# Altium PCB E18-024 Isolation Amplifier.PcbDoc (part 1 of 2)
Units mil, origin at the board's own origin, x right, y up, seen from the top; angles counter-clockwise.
Board outline 5740 x 5970 mil, 4 copper layers (Component Side, V+, V-, Ground), stack 33.234 mil thick; 342 components, 165 nets, 939 pads, 4 vias.
Unrouted connection lines stored in the file: 473.
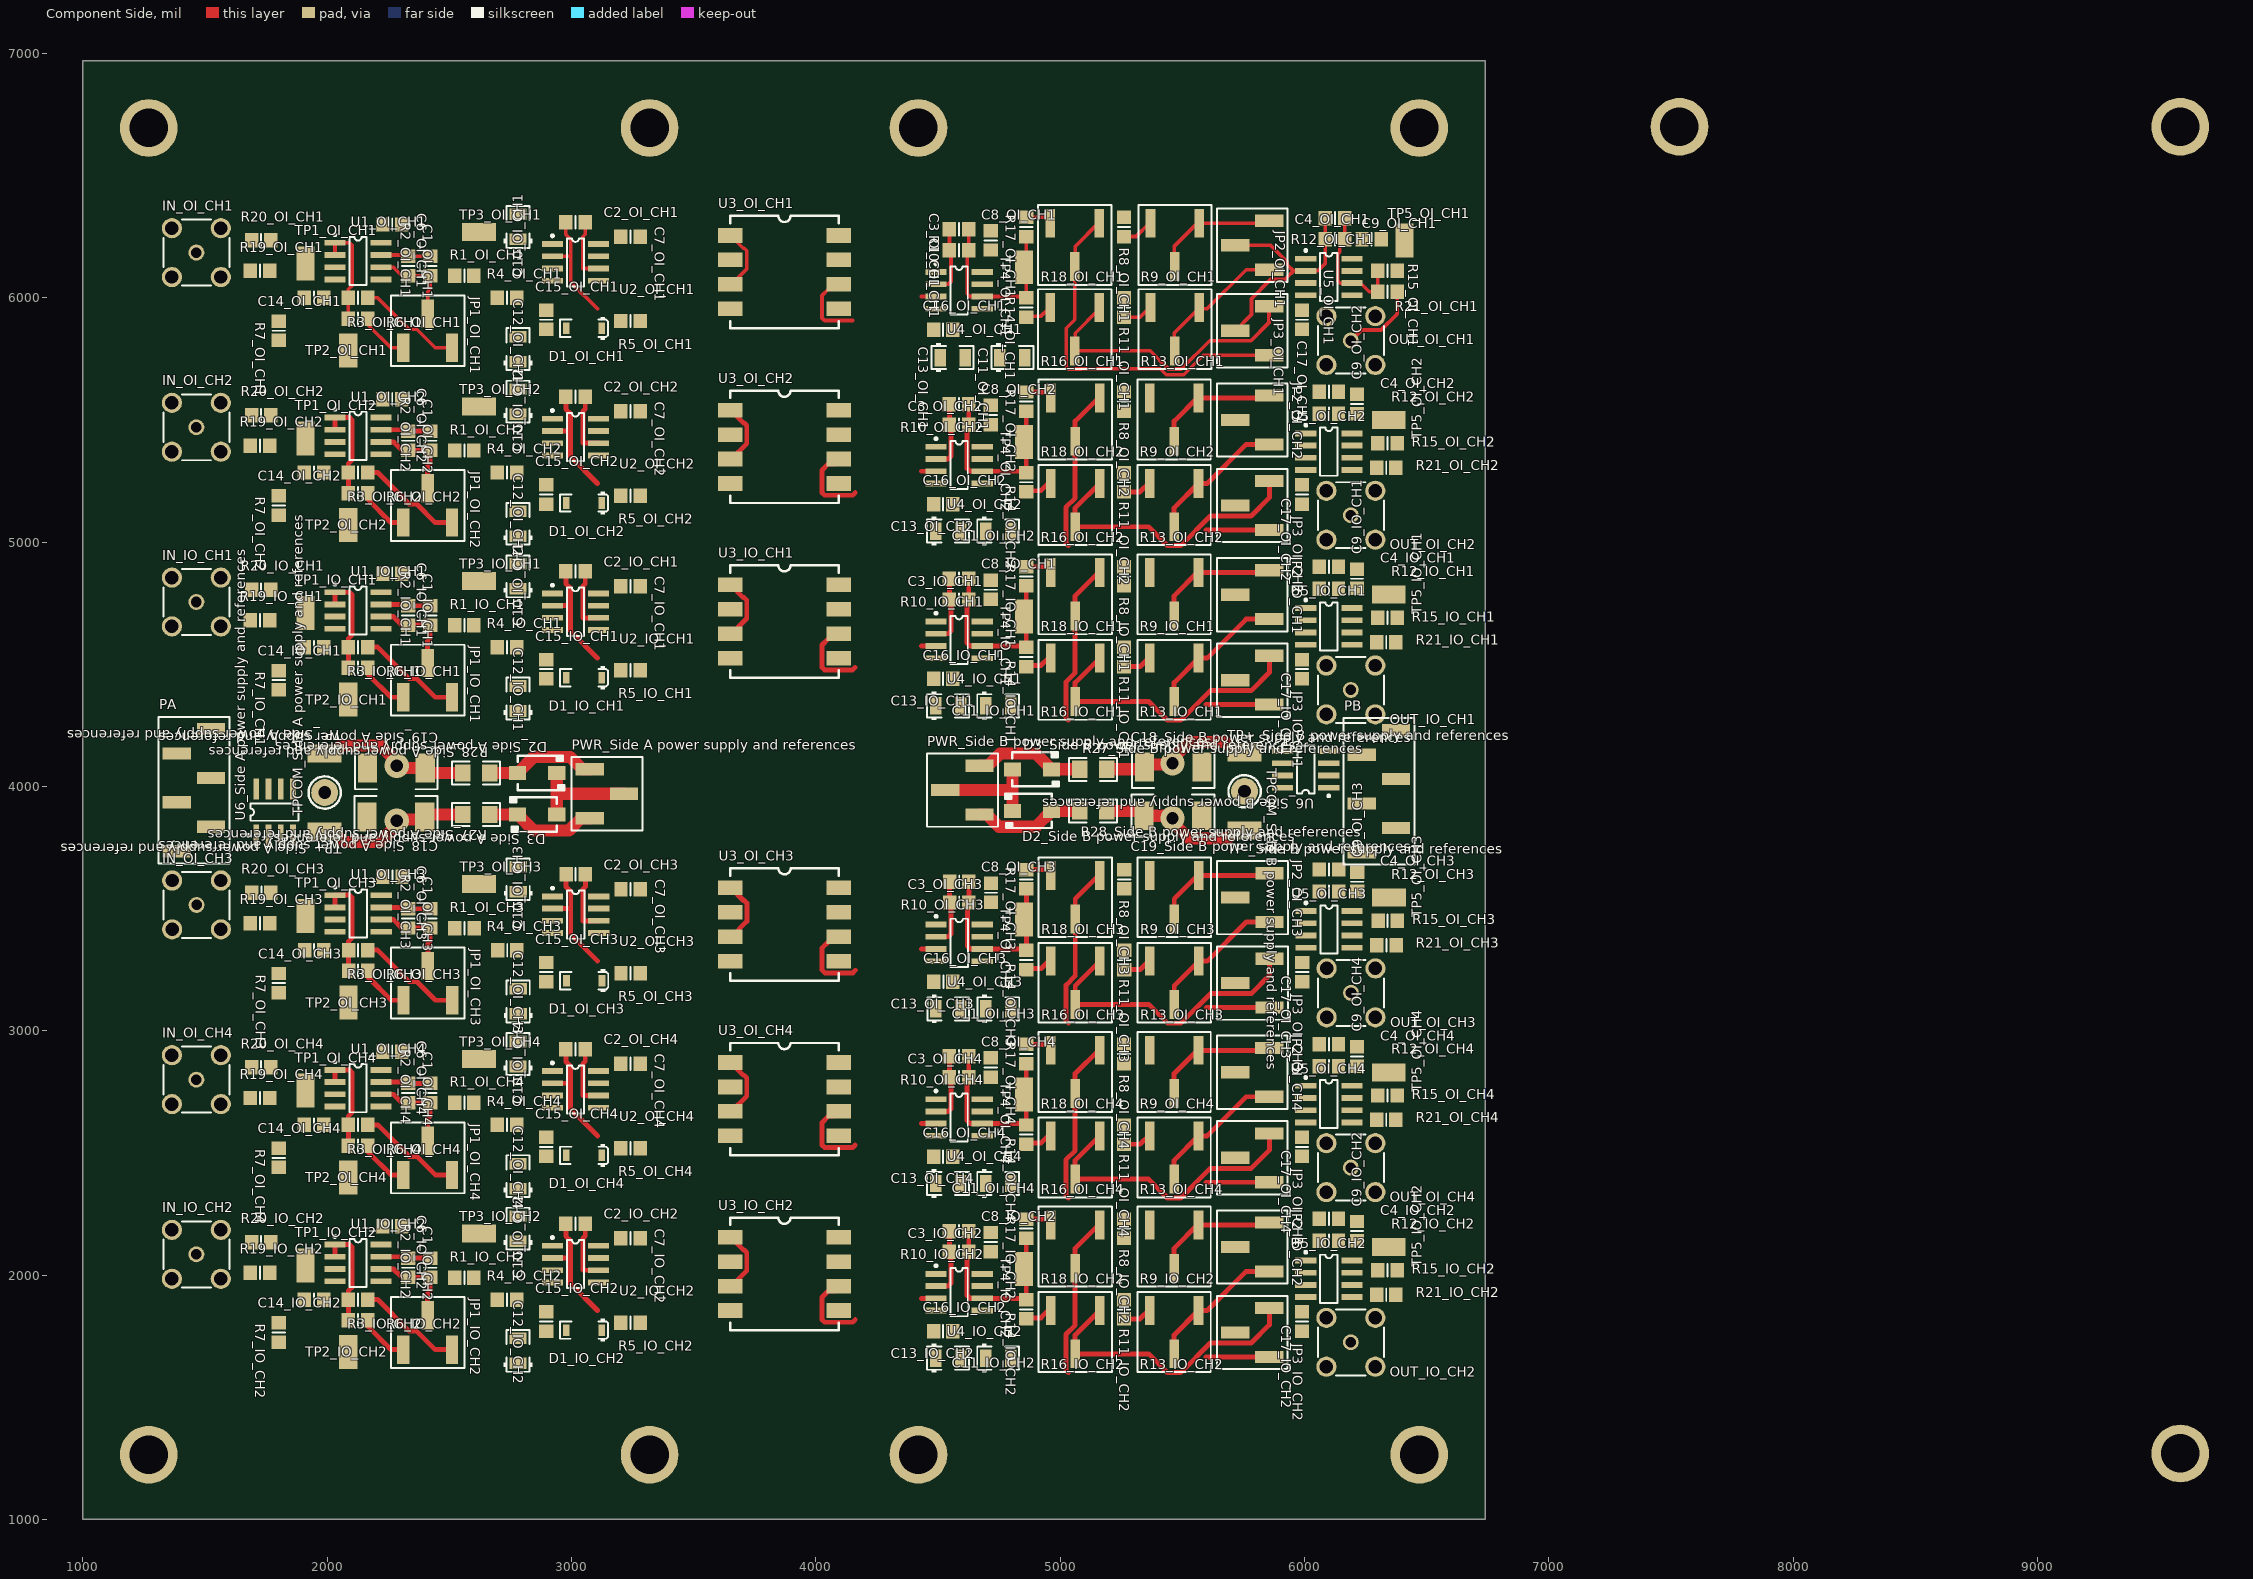
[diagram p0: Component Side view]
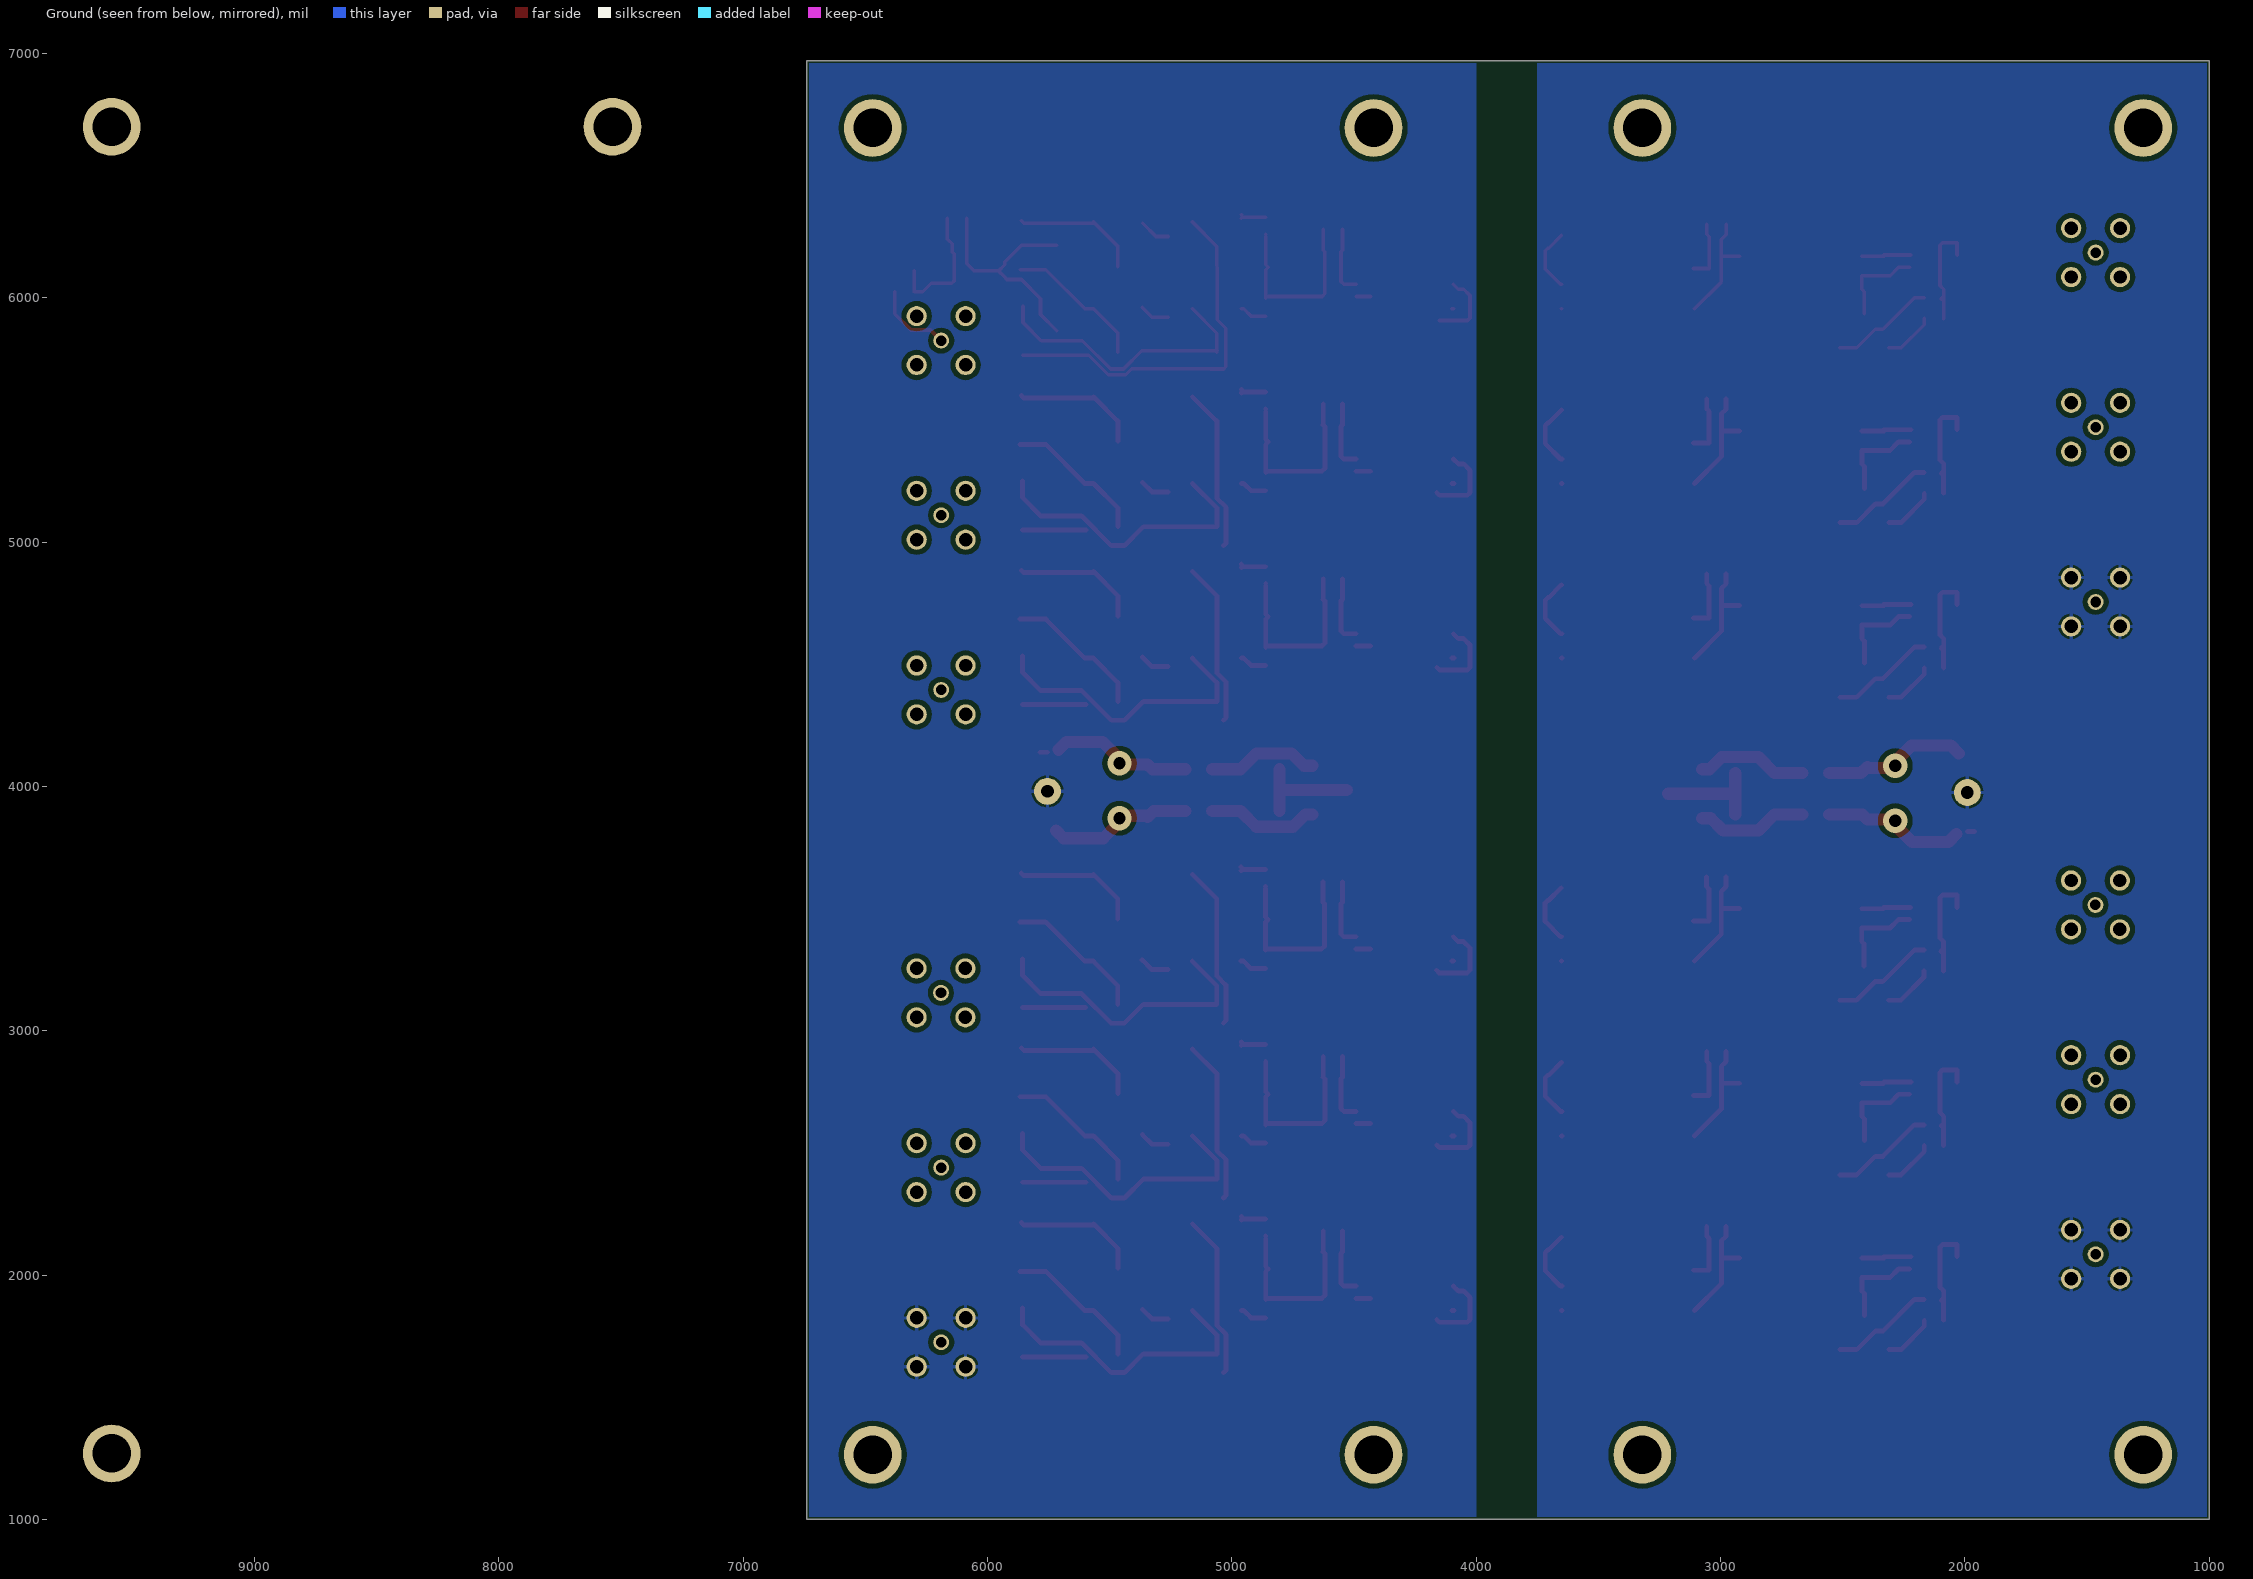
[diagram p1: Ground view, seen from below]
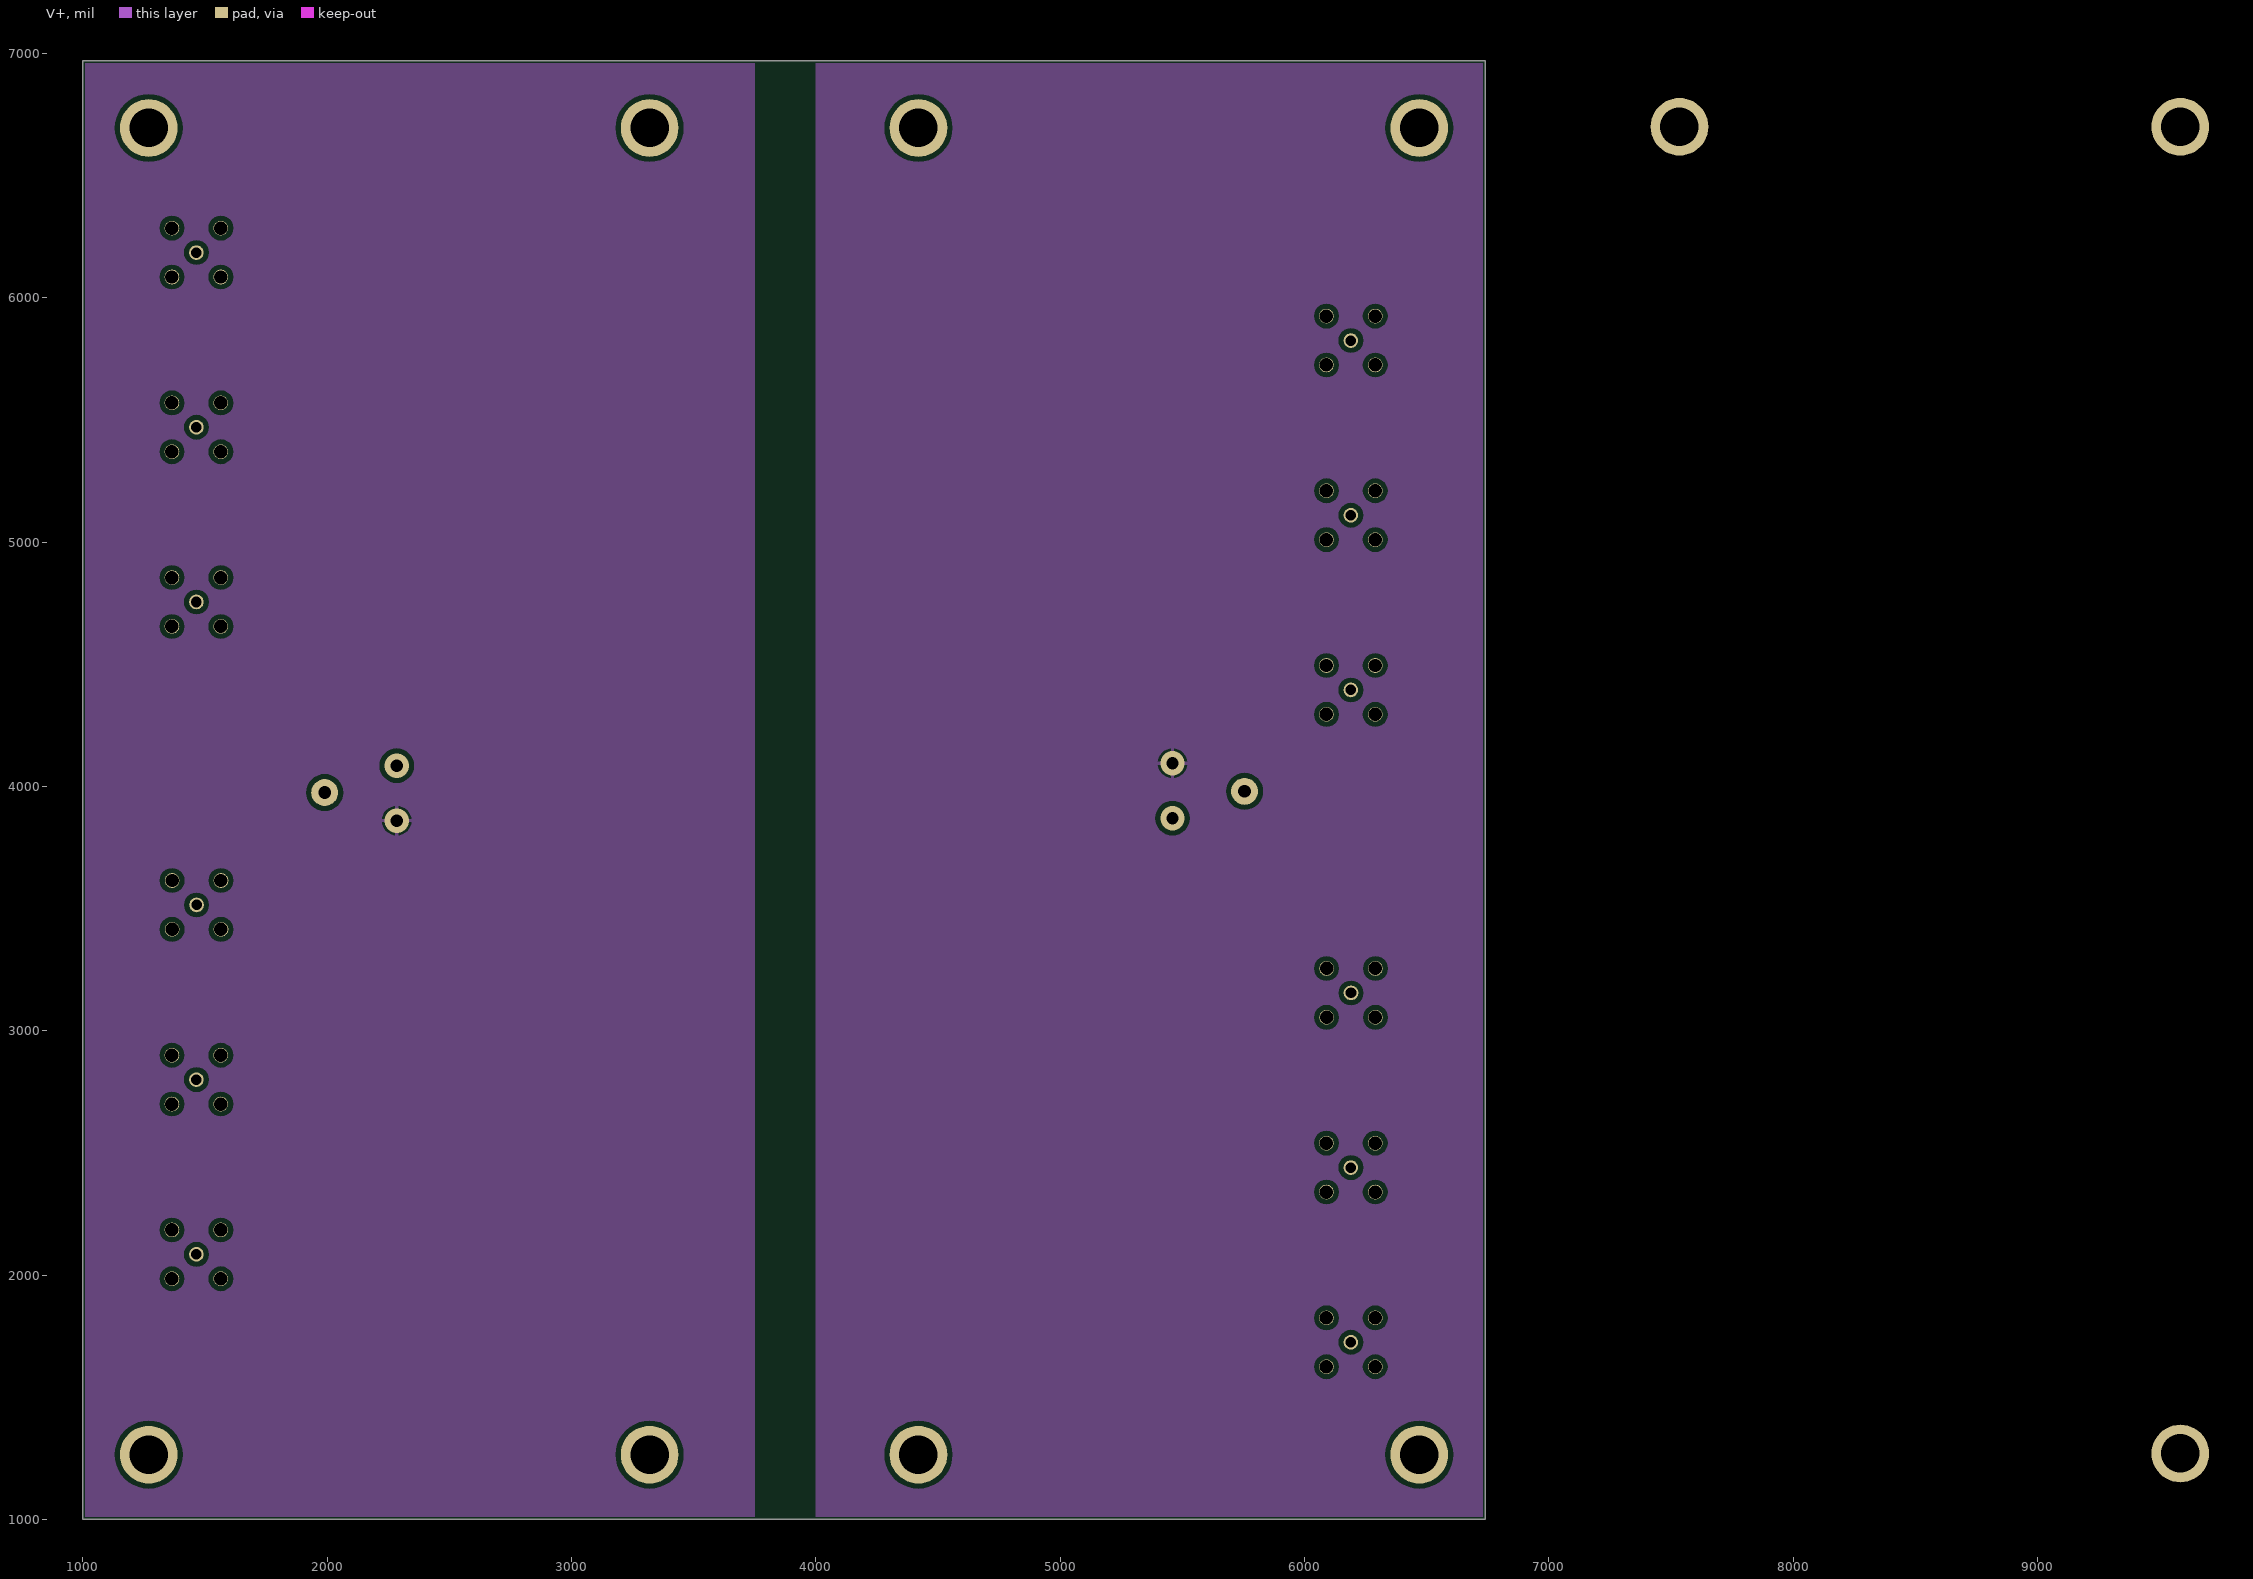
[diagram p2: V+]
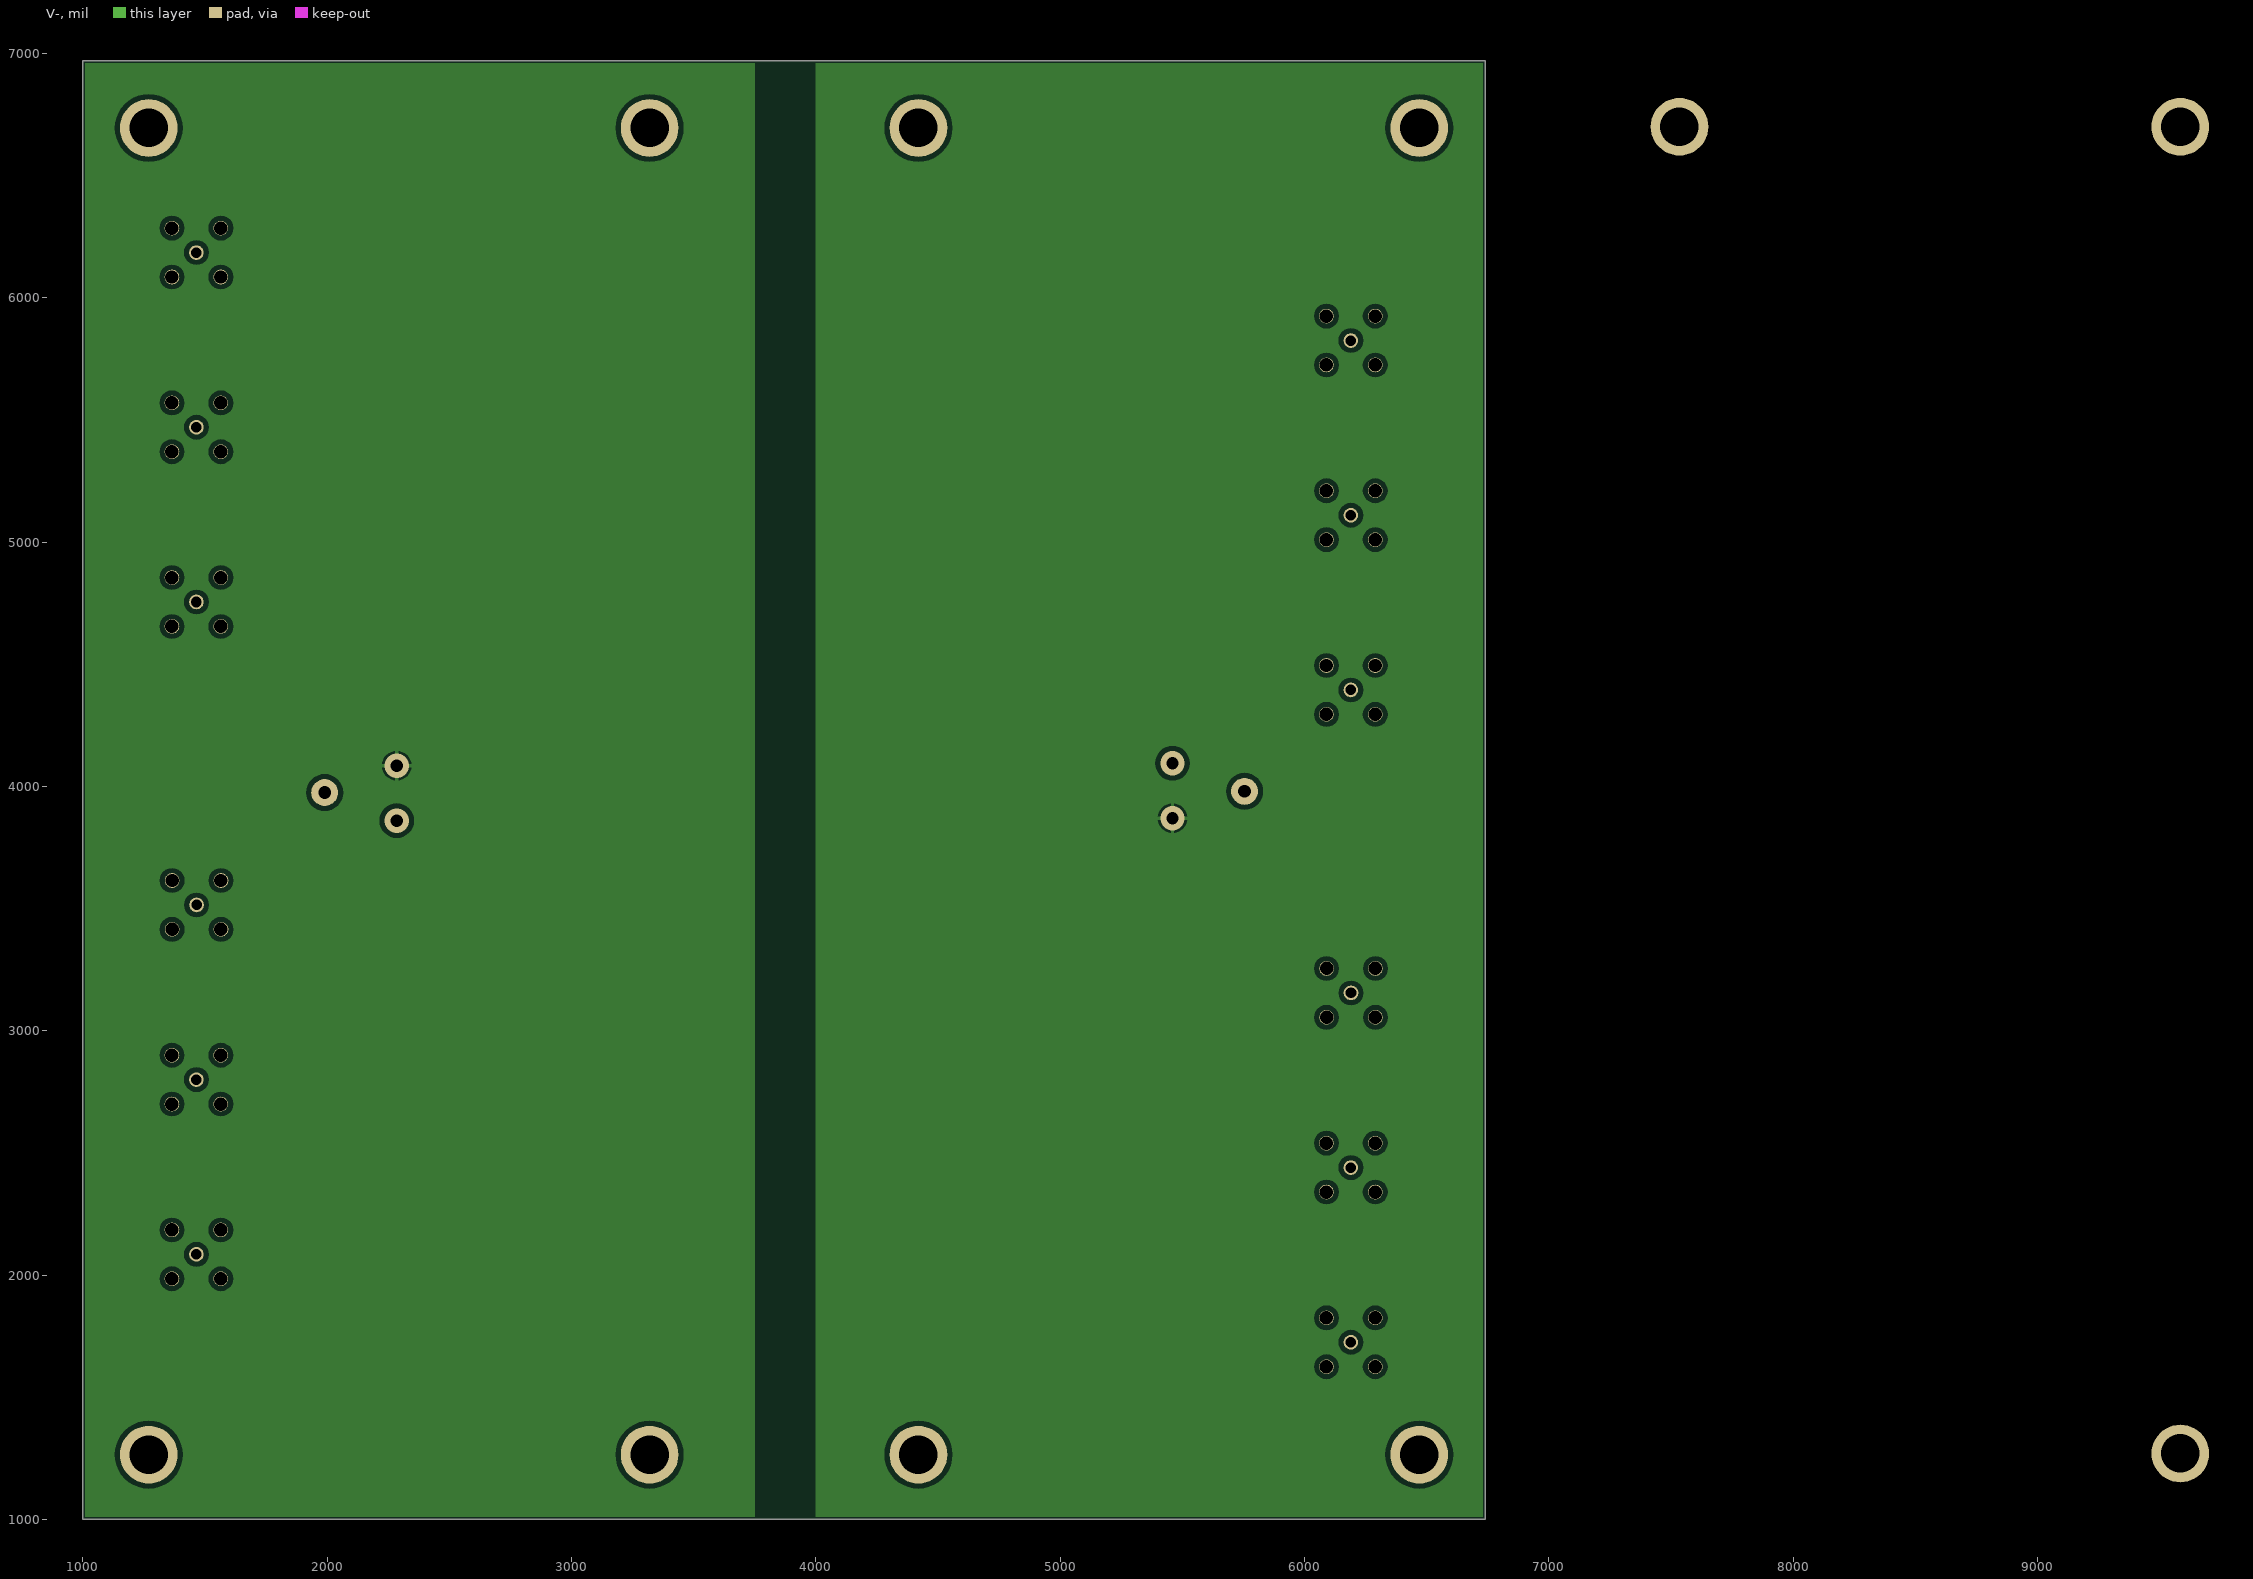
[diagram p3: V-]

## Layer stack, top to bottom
Top Solder: solder mask 0.4, Solder Resist, Dk 3.5
Component Side: signal copper 1.4
Dielectric 1: core 12.6, FR-4, Dk 4.8
V+: signal copper 1.417
Dielectric 4: prepreg 5, Dk 4.2
V-: signal copper 1.417
Dielectric 3: core 10, Dk 4.2
Ground: signal copper 1.4
Bottom Solder: solder mask 0.4, Solder Resist, Dk 3.5

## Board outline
1000,1000 1000,6970 6740,6970 6740,1000

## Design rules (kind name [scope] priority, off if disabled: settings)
AcuteAngle [All] p1: minimum=3.00000000000000E+0001 checktracksonly=FALSE
Clearance Polygon_Pour [InPolygon] p1: gap=20 ignorepadtopadclearanceinfootprint=FALSE except(0: Arc-Hole Track-Hole SMDPad-Hole THPad-Hole Via-Hole Fill-Hole Poly-Hole Region-Hole Text-Hole)
Clearance [All] p2: gap=8 ignorepadtopadclearanceinfootprint=FALSE except(0: Arc-Hole Track-Hole SMDPad-Hole THPad-Hole Via-Hole Fill-Hole Poly-Hole Region-Hole Text-Hole)
HoleSize [All] p1: absolutevalues=TRUE maxlimit=250 minlimit=20 maxpercent=80.000 minpercent=20.000
MinimumAnnularRing [All] p1: minimumring=10
MinimumSolderMaskSliver [All] p1: minsoldermaskwidth=2
MinimumSolderMaskSliver SilkscreenOverComponentPads [All] p2: minsoldermaskwidth=10
PolygonConnect PolygonConnect_1 [All vs IsNamedPolygon('GND_L01_P023') or IsNamedPolygon('GND_L02_P022') or IsNamedPolygon('GND_L03_P021') or IsNamedPolygon('GND_L04_P019')] p1: connectstyle=Direct reliefconductorwidth=10 reliefentries=4 polygonreliefangle="90 Angle" airgapwidth=10
PolygonConnect PolygonViaConnect [(InNet('GND') AND IsVia) OR (InNet('V+') AND IsVia) OR (InNet('V-') AND IsVia)] p2: connectstyle=Direct reliefconductorwidth=15 reliefentries=4 polygonreliefangle="45 Angle" airgapwidth=10
PolygonConnect [All] p3: connectstyle=Relief reliefconductorwidth=15 reliefentries=4 polygonreliefangle="90 Angle" airgapwidth=10
RoomDefinition "E18-024 Isolation Amplifier Top" [InComponentClass('E18-024 Isolation Amplifier Top')] p1: confinementstyle=ConfineOut formatcopy=TRUE lockcomponents=FALSE outline 0,0 160,0 160,265 0,265
RoomDefinition "E18-024 Isolation Amplifier Top A" [InComponentClass('Top A')] p2: confinementstyle=ConfineIn formatcopy=TRUE lockcomponents=FALSE outline 1615,4305 1615,3670 1295,3670 1295,4305
RoomDefinition "Side B power supply and references" [InComponentClass('Side B power supply and references')] p3: confinementstyle=ConfineIn formatcopy=TRUE lockcomponents=FALSE outline 6190,4240 4425,4240 4425,3715 6190,3715
RoomDefinition "Side A power supply and references" [InComponentClass('Side A power supply and references')] p4: confinementstyle=ConfineIn formatcopy=TRUE lockcomponents=FALSE outline 1555,3715 3320,3715 3320,4240 1555,4240
RoomDefinition OI_CH4 [InComponentClass('OI_CH4')] p5: confinementstyle=ConfineIn formatcopy=TRUE lockcomponents=FALSE outline 1305,2285 6461.54,2285 6461.54,3000 1305,3000
RoomDefinition OI_CH3 [InComponentClass('OI_CH3')] p6: confinementstyle=ConfineIn formatcopy=TRUE lockcomponents=FALSE outline 1305.63,3000 6462.17,3000 6462.17,3715 1305.63,3715
RoomDefinition OI_CH2 [InComponentClass('OI_CH2')] p7: confinementstyle=ConfineIn formatcopy=TRUE lockcomponents=FALSE outline 1305,4955 6461.54,4955 6461.54,5670 1305,5670
RoomDefinition OI_CH1 [InComponentClass('OI_CH1')] p8: confinementstyle=ConfineIn formatcopy=TRUE lockcomponents=FALSE outline 1305,5670 6470,5670 6470,6385 1305,6385
RoomDefinition IO_CH2 [InComponentClass('IO_CH2')] p9: confinementstyle=ConfineIn formatcopy=TRUE lockcomponents=FALSE outline 1305,1570 6461.54,1570 6461.54,2285 1305,2285
RoomDefinition IO_CH1 [InComponentClass('IO_CH1')] p10: confinementstyle=ConfineIn formatcopy=TRUE lockcomponents=FALSE outline 1305,4240 6461.54,4240 6461.54,4955 1305,4955
RoutingVias [All] p1: holewidth=28 width=50 viastyle="Through Hole" minholewidth=28 minwidth=50 maxholewidth=28 maxwidth=50
SilkToSilkClearance [All] p1: silktosilkclearance=2
SilkToSolderMaskClearance [IsPad] p1: minsilkscreentomaskgap=5.9 clearancetoexposedcopper=TRUE
SolderMaskExpansion [All] p1: expansion=4
Width [All] p1: maxlimit=100 minlimit=8 preferedwidth=20 midlayer1_minwidth=10 midlayer2_minwidth=10 minimp=50.000000 maximp=50.000000 favimp=50.000000
26 further rules are at their usual default settings.

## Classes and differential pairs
component class "E18-024 Isolation Amplifier Top": PA PB
channel class "E18-024 Power supply and references": "Side A power supply and references" "Side B power supply and references"
channel class "E18-024 Channel": IO_CH1 IO_CH2 OI_CH1 OI_CH2 OI_CH3 OI_CH4
component class "Side B power supply and references": "C18_Side B power supply and references" "C19_Side B power supply and references" "D2_Side B power supply and references" "D3_Side B power supply and references" "PWR_Side B power supply and references" "R27_Side B power supply and references" "R28_Side B power supply and references" "TP+_Side B power supply and references" "TP-_Side B power supply and references" "TPCOM_Side B power supply and references" "U6_Side B power supply and references"
component class "Side A power supply and references": "C18_Side A power supply and references" "C19_Side A power supply and references" "D2_Side A power supply and references" "D3_Side A power supply and references" "PWR_Side A power supply and references" "R27_Side A power supply and references" "R28_Side A power supply and references" "TP+_Side A power supply and references" "TP-_Side A power supply and references" "TPCOM_Side A power supply and references" "U6_Side A power supply and references"
component class OI_CH4: C1_OI_CH4 C2_OI_CH4 C3_OI_CH4 C4_OI_CH4 C6_OI_CH4 C7_OI_CH4 C8_OI_CH4 C9_OI_CH4 C10_OI_CH4 C11_OI_CH4 C12_OI_CH4 C13_OI_CH4 C14_OI_CH4 C15_OI_CH4 C16_OI_CH4 C17_OI_CH4 D1_OI_CH4 IN_OI_CH4 JP1_OI_CH4 JP2_OI_CH4 JP3_OI_CH4 OUT_OI_CH4 R1_OI_CH4 R2_OI_CH4 R3_OI_CH4 R4_OI_CH4 R5_OI_CH4 R6_OI_CH4 R7_OI_CH4 R8_OI_CH4 R9_OI_CH4 R10_OI_CH4 R11_OI_CH4 R12_OI_CH4 R13_OI_CH4 R14_OI_CH4 R15_OI_CH4 R16_OI_CH4 R17_OI_CH4 R18_OI_CH4 R19_OI_CH4 R20_OI_CH4 R21_OI_CH4 TP1_OI_CH4 TP2_OI_CH4 TP3_OI_CH4 TP4_OI_CH4 TP5_OI_CH4 U1_OI_CH4 U2_OI_CH4 U3_OI_CH4 U4_OI_CH4 U5_OI_CH4
component class OI_CH3: C1_OI_CH3 C2_OI_CH3 C3_OI_CH3 C4_OI_CH3 C6_OI_CH3 C7_OI_CH3 C8_OI_CH3 C9_OI_CH3 C10_OI_CH3 C11_OI_CH3 C12_OI_CH3 C13_OI_CH3 C14_OI_CH3 C15_OI_CH3 C16_OI_CH3 C17_OI_CH3 D1_OI_CH3 IN_OI_CH3 JP1_OI_CH3 JP2_OI_CH3 JP3_OI_CH3 OUT_OI_CH3 R1_OI_CH3 R2_OI_CH3 R3_OI_CH3 R4_OI_CH3 R5_OI_CH3 R6_OI_CH3 R7_OI_CH3 R8_OI_CH3 R9_OI_CH3 R10_OI_CH3 R11_OI_CH3 R12_OI_CH3 R13_OI_CH3 R14_OI_CH3 R15_OI_CH3 R16_OI_CH3 R17_OI_CH3 R18_OI_CH3 R19_OI_CH3 R20_OI_CH3 R21_OI_CH3 TP1_OI_CH3 TP2_OI_CH3 TP3_OI_CH3 TP4_OI_CH3 TP5_OI_CH3 U1_OI_CH3 U2_OI_CH3 U3_OI_CH3 U4_OI_CH3 U5_OI_CH3
component class OI_CH2: C1_OI_CH2 C2_OI_CH2 C3_OI_CH2 C4_OI_CH2 C6_OI_CH2 C7_OI_CH2 C8_OI_CH2 C9_OI_CH2 C10_OI_CH2 C11_OI_CH2 C12_OI_CH2 C13_OI_CH2 C14_OI_CH2 C15_OI_CH2 C16_OI_CH2 C17_OI_CH2 D1_OI_CH2 IN_OI_CH2 JP1_OI_CH2 JP2_OI_CH2 JP3_OI_CH2 OUT_OI_CH2 R1_OI_CH2 R2_OI_CH2 R3_OI_CH2 R4_OI_CH2 R5_OI_CH2 R6_OI_CH2 R7_OI_CH2 R8_OI_CH2 R9_OI_CH2 R10_OI_CH2 R11_OI_CH2 R12_OI_CH2 R13_OI_CH2 R14_OI_CH2 R15_OI_CH2 R16_OI_CH2 R17_OI_CH2 R18_OI_CH2 R19_OI_CH2 R20_OI_CH2 R21_OI_CH2 TP1_OI_CH2 TP2_OI_CH2 TP3_OI_CH2 TP4_OI_CH2 TP5_OI_CH2 U1_OI_CH2 U2_OI_CH2 U3_OI_CH2 U4_OI_CH2 U5_OI_CH2
component class OI_CH1: C1_OI_CH1 C2_OI_CH1 C3_OI_CH1 C4_OI_CH1 C6_OI_CH1 C7_OI_CH1 C8_OI_CH1 C9_OI_CH1 C10_OI_CH1 C11_OI_CH1 C12_OI_CH1 C13_OI_CH1 C14_OI_CH1 C15_OI_CH1 C16_OI_CH1 C17_OI_CH1 D1_OI_CH1 IN_OI_CH1 JP1_OI_CH1 JP2_OI_CH1 JP3_OI_CH1 OUT_OI_CH1 R1_OI_CH1 R2_OI_CH1 R3_OI_CH1 R4_OI_CH1 R5_OI_CH1 R6_OI_CH1 R7_OI_CH1 R8_OI_CH1 R9_OI_CH1 R10_OI_CH1 R11_OI_CH1 R12_OI_CH1 R13_OI_CH1 R14_OI_CH1 R15_OI_CH1 R16_OI_CH1 R17_OI_CH1 R18_OI_CH1 R19_OI_CH1 R20_OI_CH1 R21_OI_CH1 TP1_OI_CH1 TP2_OI_CH1 TP3_OI_CH1 TP4_OI_CH1 TP5_OI_CH1 U1_OI_CH1 U2_OI_CH1 U3_OI_CH1 U4_OI_CH1 U5_OI_CH1
component class IO_CH2: C1_IO_CH2 C2_IO_CH2 C3_IO_CH2 C4_IO_CH2 C6_IO_CH2 C7_IO_CH2 C8_IO_CH2 C9_IO_CH2 C10_IO_CH2 C11_IO_CH2 C12_IO_CH2 C13_IO_CH2 C14_IO_CH2 C15_IO_CH2 C16_IO_CH2 C17_IO_CH2 D1_IO_CH2 IN_IO_CH2 JP1_IO_CH2 JP2_IO_CH2 JP3_IO_CH2 OUT_IO_CH2 R1_IO_CH2 R2_IO_CH2 R3_IO_CH2 R4_IO_CH2 R5_IO_CH2 R6_IO_CH2 R7_IO_CH2 R8_IO_CH2 R9_IO_CH2 R10_IO_CH2 R11_IO_CH2 R12_IO_CH2 R13_IO_CH2 R14_IO_CH2 R15_IO_CH2 R16_IO_CH2 R17_IO_CH2 R18_IO_CH2 R19_IO_CH2 R20_IO_CH2 R21_IO_CH2 TP1_IO_CH2 TP2_IO_CH2 TP3_IO_CH2 TP4_IO_CH2 TP5_IO_CH2 U1_IO_CH2 U2_IO_CH2 U3_IO_CH2 U4_IO_CH2 U5_IO_CH2
component class IO_CH1: C1_IO_CH1 C2_IO_CH1 C3_IO_CH1 C4_IO_CH1 C6_IO_CH1 C7_IO_CH1 C8_IO_CH1 C9_IO_CH1 C10_IO_CH1 C11_IO_CH1 C12_IO_CH1 C13_IO_CH1 C14_IO_CH1 C15_IO_CH1 C16_IO_CH1 C17_IO_CH1 D1_IO_CH1 IN_IO_CH1 JP1_IO_CH1 JP2_IO_CH1 JP3_IO_CH1 OUT_IO_CH1 R1_IO_CH1 R2_IO_CH1 R3_IO_CH1 R4_IO_CH1 R5_IO_CH1 R6_IO_CH1 R7_IO_CH1 R8_IO_CH1 R9_IO_CH1 R10_IO_CH1 R11_IO_CH1 R12_IO_CH1 R13_IO_CH1 R14_IO_CH1 R15_IO_CH1 R16_IO_CH1 R17_IO_CH1 R18_IO_CH1 R19_IO_CH1 R20_IO_CH1 R21_IO_CH1 TP1_IO_CH1 TP2_IO_CH1 TP3_IO_CH1 TP4_IO_CH1 TP5_IO_CH1 U1_IO_CH1 U2_IO_CH1 U3_IO_CH1 U4_IO_CH1 U5_IO_CH1

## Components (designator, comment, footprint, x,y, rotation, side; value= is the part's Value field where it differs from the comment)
C1_IO_CH1 "10pF" 6-0805_M 2421.54,4700 r270 top (schematic designator C1)
C1_IO_CH2 "10pF" 6-0805_M 2421.54,2030 r270 top (schematic designator C1)
C1_OI_CH1 "10pF" 6-0805_M 2421.54,6130 r270 top (schematic designator C1)
C1_OI_CH2 "10pF" 6-0805_M 2421.54,5415 r270 top (schematic designator C1)
C1_OI_CH3 "10pF" 6-0805_M 2422.17,3460 r270 top (schematic designator C1)
C1_OI_CH4 "10pF" 6-0805_M 2421.54,2745 r270 top (schematic designator C1)
C2_IO_CH1 "10pF" 6-0805_M 3016.54,4880 r180 top (schematic designator C2)
C2_IO_CH2 "10pF" 6-0805_M 3016.54,2210 r180 top (schematic designator C2)
C2_OI_CH1 "10pF" 6-0805_M 3016.54,6310 r180 top (schematic designator C2)
C2_OI_CH2 "10pF" 6-0805_M 3016.54,5595 r180 top (schematic designator C2)
C2_OI_CH3 "10pF" 6-0805_M 3017.17,3640 r180 top (schematic designator C2)
C2_OI_CH4 "10pF" 6-0805_M 3016.54,2925 r180 top (schematic designator C2)
C3_IO_CH1 "10pF" 6-0805_M 4586.54,4850 r180 top (schematic designator C3)
C3_IO_CH2 "10pF" 6-0805_M 4586.54,2180 r180 top (schematic designator C3)
C3_OI_CH1 "10pF" 6-0805_M 4586.54,6280 r180 top (schematic designator C3)
C3_OI_CH2 "10pF" 6-0805_M 4586.54,5565 r180 top (schematic designator C3)
C3_OI_CH3 "10pF" 6-0805_M 4587.17,3610 r180 top (schematic designator C3)
C3_OI_CH4 "10pF" 6-0805_M 4586.54,2895 r180 top (schematic designator C3)
C4_IO_CH1 "10pF" 6-0805_M 6100,4900 r180 top (schematic designator C4)
C4_IO_CH2 "10pF" 6-0805_M 6100,2230 r180 top (schematic designator C4)
C4_OI_CH1 "10pF" 6-0805_M 6125,6325 r180 top (schematic designator C4)
C4_OI_CH2 "10pF" 6-0805_M 6100,5615 r180 top (schematic designator C4)
C4_OI_CH3 "10pF" 6-0805_M 6100.63,3660 r180 top (schematic designator C4)
C4_OI_CH4 "10pF" 6-0805_M 6100,2945 r180 top (schematic designator C4)
C6_IO_CH1 "100nF" 6-0805_M 2266.54,4870 r180 top (schematic designator C6)
C6_IO_CH2 "100nF" 6-0805_M 2266.54,2200 r180 top (schematic designator C6)
C6_OI_CH1 "100nF" 6-0805_M 2266.54,6300 r180 top (schematic designator C6)
C6_OI_CH2 "100nF" 6-0805_M 2266.54,5585 r180 top (schematic designator C6)
C6_OI_CH3 "100nF" 6-0805_M 2267.17,3630 r180 top (schematic designator C6)
C6_OI_CH4 "100nF" 6-0805_M 2266.54,2915 r180 top (schematic designator C6)
C7_IO_CH1 "100nF" 6-0805_M 3241.54,4820 r180 top (schematic designator C7)
C7_IO_CH2 "100nF" 6-0805_M 3241.54,2150 r180 top (schematic designator C7)
C7_OI_CH1 "100nF" 6-0805_M 3241.54,6250 r180 top (schematic designator C7)
C7_OI_CH2 "100nF" 6-0805_M 3241.54,5535 r180 top (schematic designator C7)
C7_OI_CH3 "100nF" 6-0805_M 3242.17,3580 r180 top (schematic designator C7)
C7_OI_CH4 "100nF" 6-0805_M 3241.54,2865 r180 top (schematic designator C7)
C8_IO_CH1 "100nF" 6-0805_M 4716.54,4805 r90 top (schematic designator C8)
C8_IO_CH2 "100nF" 6-0805_M 4716.54,2135 r90 top (schematic designator C8)
C8_OI_CH1 "100nF" 6-0805_M 4716.54,6235 r90 top (schematic designator C8)
C8_OI_CH2 "100nF" 6-0805_M 4716.54,5520 r90 top (schematic designator C8)
C8_OI_CH3 "100nF" 6-0805_M 4717.17,3565 r90 top (schematic designator C8)
C8_OI_CH4 "100nF" 6-0805_M 4716.54,2850 r90 top (schematic designator C8)
C9_IO_CH1 "100nF" 6-0805_M 6215,4850 r270 top (schematic designator C9)
C9_IO_CH2 "100nF" 6-0805_M 6215,2180 r270 top (schematic designator C9)
C9_OI_CH1 "100nF" 6-0805_M 6275,6240 r180 top (schematic designator C9)
C9_OI_CH2 "100nF" 6-0805_M 6215,5565 r270 top (schematic designator C9)
C9_OI_CH3 "100nF" 6-0805_M 6215.63,3610 r270 top (schematic designator C9)
C9_OI_CH4 "100nF" 6-0805_M 6215,2895 r270 top (schematic designator C9)
C10_IO_CH1 "Tant Poly 10uF" CC3216 2781.54,4860 r90 top value=10uF (schematic designator C10)
C10_IO_CH2 "Tant Poly 10uF" CC3216 2781.54,2190 r90 top value=10uF (schematic designator C10)
C10_OI_CH1 "Tant Poly 10uF" CC3216 2781.54,6290 r90 top value=10uF (schematic designator C10)
C10_OI_CH2 "Tant Poly 10uF" CC3216 2781.54,5575 r90 top value=10uF (schematic designator C10)
C10_OI_CH3 "Tant Poly 10uF" CC3216 2782.17,3620 r90 top value=10uF (schematic designator C10)
C10_OI_CH4 "Tant Poly 10uF" CC3216 2781.54,2905 r90 top value=10uF (schematic designator C10)
C11_IO_CH1 "Tant Poly 10uF" CC3216 4746.54,4330 r0 top value=10uF (schematic designator C11)
C11_IO_CH2 "Tant Poly 10uF" CC3216 4746.54,1660 r0 top value=10uF (schematic designator C11)
C11_OI_CH1 "Tant Poly 10uF" CC3216 4805,5755 r0 top value=10uF (schematic designator C11)
C11_OI_CH2 "Tant Poly 10uF" CC3216 4746.54,5045 r0 top value=10uF (schematic designator C11)
C11_OI_CH3 "Tant Poly 10uF" CC3216 4747.17,3090 r0 top value=10uF (schematic designator C11)
C11_OI_CH4 "Tant Poly 10uF" CC3216 4746.54,2375 r0 top value=10uF (schematic designator C11)
C12_IO_CH1 "Tant Poly 10uF" CC3216 2781.54,4360 r90 top value=10uF (schematic designator C12)
C12_IO_CH2 "Tant Poly 10uF" CC3216 2781.54,1690 r90 top value=10uF (schematic designator C12)
C12_OI_CH1 "Tant Poly 10uF" CC3216 2781.54,5790 r90 top value=10uF (schematic designator C12)
C12_OI_CH2 "Tant Poly 10uF" CC3216 2781.54,5075 r90 top value=10uF (schematic designator C12)
C12_OI_CH3 "Tant Poly 10uF" CC3216 2782.17,3120 r90 top value=10uF (schematic designator C12)
C12_OI_CH4 "Tant Poly 10uF" CC3216 2781.54,2405 r90 top value=10uF (schematic designator C12)
C13_IO_CH1 "Tant Poly 10uF" CC3216 4541.54,4330 r0 top value=10uF (schematic designator C13)
C13_IO_CH2 "Tant Poly 10uF" CC3216 4541.54,1660 r0 top value=10uF (schematic designator C13)
C13_OI_CH1 "Tant Poly 10uF" CC3216 4560,5755 r0 top value=10uF (schematic designator C13)
C13_OI_CH2 "Tant Poly 10uF" CC3216 4541.54,5045 r0 top value=10uF (schematic designator C13)
C13_OI_CH3 "Tant Poly 10uF" CC3216 4542.17,3090 r0 top value=10uF (schematic designator C13)
C13_OI_CH4 "Tant Poly 10uF" CC3216 4541.54,2375 r0 top value=10uF (schematic designator C13)
C14_IO_CH1 "100nF" 6-0805_M 1946.54,4570 r0 top (schematic designator C14)
C14_IO_CH2 "100nF" 6-0805_M 1946.54,1900 r0 top (schematic designator C14)
C14_OI_CH1 "100nF" 6-0805_M 1946.54,6000 r0 top (schematic designator C14)
C14_OI_CH2 "100nF" 6-0805_M 1946.54,5285 r0 top (schematic designator C14)
C14_OI_CH3 "100nF" 6-0805_M 1947.17,3330 r0 top (schematic designator C14)
C14_OI_CH4 "100nF" 6-0805_M 1946.54,2615 r0 top (schematic designator C14)
C15_IO_CH1 "100nF" 6-0805_M 2896.54,4480 r90 top (schematic designator C15)
C15_IO_CH2 "100nF" 6-0805_M 2896.54,1810 r90 top (schematic designator C15)
C15_OI_CH1 "100nF" 6-0805_M 2896.54,5910 r90 top (schematic designator C15)
C15_OI_CH2 "100nF" 6-0805_M 2896.54,5195 r90 top (schematic designator C15)
C15_OI_CH3 "100nF" 6-0805_M 2897.17,3240 r90 top (schematic designator C15)
C15_OI_CH4 "100nF" 6-0805_M 2896.54,2525 r90 top (schematic designator C15)
C16_IO_CH1 "100nF" 6-0805_M 4521.54,4440 r0 top (schematic designator C16)
C16_IO_CH2 "100nF" 6-0805_M 4521.54,1770 r0 top (schematic designator C16)
C16_OI_CH1 "100nF" 6-0805_M 4521.54,5870 r0 top (schematic designator C16)
C16_OI_CH2 "100nF" 6-0805_M 4521.54,5155 r0 top (schematic designator C16)
C16_OI_CH3 "100nF" 6-0805_M 4522.17,3200 r0 top (schematic designator C16)
C16_OI_CH4 "100nF" 6-0805_M 4521.54,2485 r0 top (schematic designator C16)
C17_IO_CH1 "100nF" 6-0805_M 5990,4480 r90 top (schematic designator C17)
C17_IO_CH2 "100nF" 6-0805_M 5990,1810 r90 top (schematic designator C17)
C17_OI_CH1 "100nF" 6-0805_M 5990,5910 r90 top (schematic designator C17)
C17_OI_CH2 "100nF" 6-0805_M 5990,5195 r90 top (schematic designator C17)
C17_OI_CH3 "100nF" 6-0805_M 5990.63,3240 r90 top (schematic designator C17)
C17_OI_CH4 "100nF" 6-0805_M 5990,2525 r90 top (schematic designator C17)
"C18_Side A power supply and references" "CAP TANT POLY 100UF 25V 2917" CC7343 2400,3875 r180 top value=100u (schematic designator C18)
"C18_Side B power supply and references" "CAP TANT POLY 100UF 25V 2917" CC7343 5345,4080 r0 top value=100u (schematic designator C18)
"C19_Side A power supply and references" "CAP TANT POLY 100UF 25V 2917" CC7343 2165,4075 r0 top value=100u (schematic designator C19)
"C19_Side B power supply and references" "CAP TANT POLY 100UF 25V 2917" CC7343 5580,3880 r180 top value=100u (schematic designator C19)
D1_IO_CH1 "1N4148W" SOD-123 3051.54,4445 r0 top (schematic designator D1)
D1_IO_CH2 "1N4148W" SOD-123 3051.54,1775 r0 top (schematic designator D1)
D1_OI_CH1 "1N4148W" SOD-123 3051.54,5875 r0 top (schematic designator D1)
D1_OI_CH2 "1N4148W" SOD-123 3051.54,5160 r0 top (schematic designator D1)
D1_OI_CH3 "1N4148W" SOD-123 3052.17,3205 r0 top (schematic designator D1)
D1_OI_CH4 "1N4148W" SOD-123 3051.54,2490 r0 top (schematic designator D1)
"D2_Side A power supply and references" "SMAZ18-13-F" SMAJ 2860,3885 r180 top (schematic designator D2)
"D2_Side B power supply and references" "SMAZ18-13-F" SMAJ 4885,4070 r0 top (schematic designator D2)
"D3_Side A power supply and references" "SMAZ18-13-F" SMAJ 2860,4055 r0 top (schematic designator D3)
"D3_Side B power supply and references" "SMAZ18-13-F" SMAJ 4885,3900 r180 top (schematic designator D3)
IN_IO_CH1 "SMB Male Vertical Mount" SMB_Male_Vertical 1465,4755 r0 top (schematic designator IN)
IN_IO_CH2 "SMB Male Vertical Mount" SMB_Male_Vertical 1465,2085 r0 top (schematic designator IN)
IN_OI_CH1 "SMB Male Vertical Mount" SMB_Male_Vertical 1465,6185 r0 top (schematic designator IN)
IN_OI_CH2 "SMB Male Vertical Mount" SMB_Male_Vertical 1465,5470 r0 top (schematic designator IN)
IN_OI_CH3 "SMB Male Vertical Mount" SMB_Male_Vertical 1465.63,3515 r0 top (schematic designator IN)
IN_OI_CH4 "SMB Male Vertical Mount" SMB_Male_Vertical 1465,2800 r0 top (schematic designator IN)
JP1_IO_CH1 "JMPR" "HDR1X3 SMD" 2511.54,4365 r180 top (schematic designator JP1)
JP1_IO_CH2 "JMPR" "HDR1X3 SMD" 2511.54,1695 r180 top (schematic designator JP1)
JP1_OI_CH1 "JMPR" "HDR1X3 SMD" 2511.54,5795 r180 top (schematic designator JP1)
JP1_OI_CH2 "JMPR" "HDR1X3 SMD" 2511.54,5080 r180 top (schematic designator JP1)
JP1_OI_CH3 "JMPR" "HDR1X3 SMD" 2512.17,3125 r180 top (schematic designator JP1)
JP1_OI_CH4 "JMPR" "HDR1X3 SMD" 2511.54,2410 r180 top (schematic designator JP1)
JP2_IO_CH1 "JMPR" "HDR1X3 SMD" 5856.54,4885 r270 top (schematic designator JP2)
JP2_IO_CH2 "JMPR" "HDR1X3 SMD" 5856.54,2215 r270 top (schematic designator JP2)
JP2_OI_CH1 "JMPR" "HDR1X3 SMD" 5856.54,6315 r270 top (schematic designator JP2)
JP2_OI_CH2 "JMPR" "HDR1X3 SMD" 5856.54,5600 r270 top (schematic designator JP2)
JP2_OI_CH3 "JMPR" "HDR1X3 SMD" 5857.17,3645 r270 top (schematic designator JP2)
JP2_OI_CH4 "JMPR" "HDR1X3 SMD" 5856.54,2930 r270 top (schematic designator JP2)
JP3_IO_CH1 "JMPR" "HDR1X3 SMD" 5856.54,4535 r270 top (schematic designator JP3)
JP3_IO_CH2 "JMPR" "HDR1X3 SMD" 5856.54,1865 r270 top (schematic designator JP3)
JP3_OI_CH1 "JMPR" "HDR1X3 SMD" 5856.54,5965 r270 top (schematic designator JP3)
JP3_OI_CH2 "JMPR" "HDR1X3 SMD" 5856.54,5250 r270 top (schematic designator JP3)
JP3_OI_CH3 "JMPR" "HDR1X3 SMD" 5857.17,3295 r270 top (schematic designator JP3)
JP3_OI_CH4 "JMPR" "HDR1X3 SMD" 5856.54,2580 r270 top (schematic designator JP3)
OUT_IO_CH1 "SMB Male Vertical Mount" SMB_Male_Vertical 6190,4395 r0 top (schematic designator OUT)
OUT_IO_CH2 "SMB Male Vertical Mount" SMB_Male_Vertical 6190,1725 r0 top (schematic designator OUT)
OUT_OI_CH1 "SMB Male Vertical Mount" SMB_Male_Vertical 6190,5825 r0 top (schematic designator OUT)
OUT_OI_CH2 "SMB Male Vertical Mount" SMB_Male_Vertical 6190,5110 r0 top (schematic designator OUT)
OUT_OI_CH3 "SMB Male Vertical Mount" SMB_Male_Vertical 6190.63,3155 r0 top (schematic designator OUT)
OUT_OI_CH4 "SMB Male Vertical Mount" SMB_Male_Vertical 6190,2440 r0 top (schematic designator OUT)
PA "HEADER 1X6" "HDR1X6 SMD" 1525,4235 r270 top
PB "HEADER 1X6" "HDR1X6 SMD" 6375,4230 r270 top
"PWR_Side A power supply and references" "JMPR" "HDR1X3 SMD" 3075,3870 r90 top (schematic designator PWR)
"PWR_Side B power supply and references" "JMPR" "HDR1X3 SMD" 4670,4085 r270 top (schematic designator PWR)
R1_IO_CH1 "10k" 6-0805_M 2561.54,4660 r0 top (schematic designator R1)
R1_IO_CH2 "10k" 6-0805_M 2561.54,1990 r0 top (schematic designator R1)
R1_OI_CH1 "10k" 6-0805_M 2561.54,6090 r0 top (schematic designator R1)
R1_OI_CH2 "10k" 6-0805_M 2561.54,5375 r0 top (schematic designator R1)
R1_OI_CH3 "10k" 6-0805_M 2562.17,3420 r0 top (schematic designator R1)
R1_OI_CH4 "10k" 6-0805_M 2561.54,2705 r0 top (schematic designator R1)
R2_IO_CH1 "1k" 6-0805_M 2332.17,4700 r270 top (schematic designator R2)
R2_IO_CH2 "1k" 6-0805_M 2332.17,2030 r270 top (schematic designator R2)
R2_OI_CH1 "1k" 6-0805_M 2332.17,6130 r270 top (schematic designator R2)
R2_OI_CH2 "1k" 6-0805_M 2332.17,5415 r270 top (schematic designator R2)
R2_OI_CH3 "1k" 6-0805_M 2332.8,3460 r270 top (schematic designator R2)
R2_OI_CH4 "1k" 6-0805_M 2332.17,2745 r270 top (schematic designator R2)
R3_IO_CH1 "2k" 6-0805_M 2126.54,4570 r180 top (schematic designator R3)
R3_IO_CH2 "2k" 6-0805_M 2126.54,1900 r180 top (schematic designator R3)
R3_OI_CH1 "2k" 6-0805_M 2126.54,6000 r180 top (schematic designator R3)
R3_OI_CH2 "2k" 6-0805_M 2126.54,5285 r180 top (schematic designator R3)
R3_OI_CH3 "2k" 6-0805_M 2127.17,3330 r180 top (schematic designator R3)
R3_OI_CH4 "2k" 6-0805_M 2126.54,2615 r180 top (schematic designator R3)
R4_IO_CH1 "39k" 6-0805_M 2736.54,4570 r0 top (schematic designator R4)
R4_IO_CH2 "39k" 6-0805_M 2736.54,1900 r0 top (schematic designator R4)
R4_OI_CH1 "39k" 6-0805_M 2736.54,6000 r0 top (schematic designator R4)
R4_OI_CH2 "39k" 6-0805_M 2736.54,5285 r0 top (schematic designator R4)
R4_OI_CH3 "39k" 6-0805_M 2737.17,3330 r0 top (schematic designator R4)
R4_OI_CH4 "39k" 6-0805_M 2736.54,2615 r0 top (schematic designator R4)
R5_IO_CH1 "680" 6-0805_M 3241.54,4475 r0 top (schematic designator R5)
R5_IO_CH2 "680" 6-0805_M 3241.54,1805 r0 top (schematic designator R5)
R5_OI_CH1 "680" 6-0805_M 3241.54,5905 r0 top (schematic designator R5)
R5_OI_CH2 "680" 6-0805_M 3241.54,5190 r0 top (schematic designator R5)
R5_OI_CH3 "680" 6-0805_M 3242.17,3235 r0 top (schematic designator R5)
R5_OI_CH4 "680" 6-0805_M 3241.54,2520 r0 top (schematic designator R5)
R6_IO_CH1 "10k" 6-0805_M 2126.54,4485 r180 top (schematic designator R6)
R6_IO_CH2 "10k" 6-0805_M 2126.54,1815 r180 top (schematic designator R6)
R6_OI_CH1 "10k" 6-0805_M 2126.54,5915 r180 top (schematic designator R6)
R6_OI_CH2 "10k" 6-0805_M 2126.54,5200 r180 top (schematic designator R6)
R6_OI_CH3 "10k" 6-0805_M 2127.17,3245 r180 top (schematic designator R6)
R6_OI_CH4 "10k" 6-0805_M 2126.54,2530 r180 top (schematic designator R6)
R7_IO_CH1 "10M" 6-0805_M 1801.54,4435 r270 top (schematic designator R7)
R7_IO_CH2 "10M" 6-0805_M 1801.54,1765 r270 top (schematic designator R7)
R7_OI_CH1 "10M" 6-0805_M 1801.54,5865 r270 top (schematic designator R7)
R7_OI_CH2 "10M" 6-0805_M 1801.54,5150 r270 top (schematic designator R7)
R7_OI_CH3 "10M" 6-0805_M 1802.17,3195 r270 top (schematic designator R7)
R7_OI_CH4 "10M" 6-0805_M 1801.54,2480 r270 top (schematic designator R7)
R8_IO_CH1 "2k" 6-0805_M 5261.54,4860 r90 top value=47.5k (schematic designator R8)
R8_IO_CH2 "2k" 6-0805_M 5261.54,2190 r90 top value=47.5k (schematic designator R8)
R8_OI_CH1 "2k" 6-0805_M 5261.54,6290 r90 top value=47.5k (schematic designator R8)
R8_OI_CH2 "2k" 6-0805_M 5261.54,5575 r90 top value=47.5k (schematic designator R8)
R8_OI_CH3 "2k" 6-0805_M 5262.17,3620 r90 top value=47.5k (schematic designator R8)
R8_OI_CH4 "2k" 6-0805_M 5261.54,2905 r90 top value=47.5k (schematic designator R8)
R9_IO_CH1 "RPot8" "POT SMD" 5566.54,4875 r180 top value=5k (schematic designator R9)
R9_IO_CH2 "RPot8" "POT SMD" 5566.54,2205 r180 top value=5k (schematic designator R9)
R9_OI_CH1 "RPot8" "POT SMD" 5570,6305 r180 top value=5k (schematic designator R9)
R9_OI_CH2 "RPot8" "POT SMD" 5566.54,5590 r180 top value=5k (schematic designator R9)
R9_OI_CH3 "RPot8" "POT SMD" 5567.17,3635 r180 top value=5k (schematic designator R9)
R9_OI_CH4 "RPot8" "POT SMD" 5566.54,2920 r180 top value=5k (schematic designator R9)
R10_IO_CH1 "39k" 6-0805_M 4586.54,4765 r0 top (schematic designator R10)
R10_IO_CH2 "39k" 6-0805_M 4586.54,2095 r0 top (schematic designator R10)
R10_OI_CH1 "39k" 6-0805_M 4586.54,6195 r0 top (schematic designator R10)
R10_OI_CH2 "39k" 6-0805_M 4586.54,5480 r0 top (schematic designator R10)
R10_OI_CH3 "39k" 6-0805_M 4587.17,3525 r0 top (schematic designator R10)
R10_OI_CH4 "39k" 6-0805_M 4586.54,2810 r0 top (schematic designator R10)
R11_IO_CH1 "9.09k" 6-0805_M 5261.54,4530 r90 top value=9.53k (schematic designator R11)
R11_IO_CH2 "9.09k" 6-0805_M 5261.54,1860 r90 top value=9.53k (schematic designator R11)
R11_OI_CH1 "9.09k" 6-0805_M 5261.54,5960 r90 top value=9.53k (schematic designator R11)
R11_OI_CH2 "9.09k" 6-0805_M 5261.54,5245 r90 top value=9.53k (schematic designator R11)
R11_OI_CH3 "9.09k" 6-0805_M 5262.17,3290 r90 top value=9.53k (schematic designator R11)
R11_OI_CH4 "9.09k" 6-0805_M 5261.54,2575 r90 top value=9.53k (schematic designator R11)
R12_IO_CH1 "2k" 6-0805_M 6100,4810 r180 top value=10k (schematic designator R12)
R12_IO_CH2 "2k" 6-0805_M 6100,2140 r180 top value=10k (schematic designator R12)
R12_OI_CH1 "2k" 6-0805_M 6125,6240 r180 top value=10k (schematic designator R12)
R12_OI_CH2 "2k" 6-0805_M 6100,5525 r180 top value=10k (schematic designator R12)
R12_OI_CH3 "2k" 6-0805_M 6100.63,3570 r180 top value=10k (schematic designator R12)
R12_OI_CH4 "2k" 6-0805_M 6100,2855 r180 top value=10k (schematic designator R12)
R13_IO_CH1 "RPot8" "POT SMD" 5566.54,4525 r180 top value=1k (schematic designator R13)
R13_IO_CH2 "RPot8" "POT SMD" 5566.54,1855 r180 top value=1k (schematic designator R13)
R13_OI_CH1 "RPot8" "POT SMD" 5570,5960 r180 top value=1k (schematic designator R13)
R13_OI_CH2 "RPot8" "POT SMD" 5566.54,5240 r180 top value=1k (schematic designator R13)
R13_OI_CH3 "RPot8" "POT SMD" 5567.17,3285 r180 top value=1k (schematic designator R13)
R13_OI_CH4 "RPot8" "POT SMD" 5566.54,2570 r180 top value=1k (schematic designator R13)
R14_IO_CH1 "2k" 6-0805_M 4861.54,4530 r90 top value=1.91k (schematic designator R14)
R14_IO_CH2 "2k" 6-0805_M 4861.54,1860 r90 top value=1.91k (schematic designator R14)
R14_OI_CH1 "2k" 6-0805_M 4861.54,5960 r90 top value=1.91k (schematic designator R14)
R14_OI_CH2 "2k" 6-0805_M 4861.54,5245 r90 top value=1.91k (schematic designator R14)
R14_OI_CH3 "2k" 6-0805_M 4862.17,3290 r90 top value=1.91k (schematic designator R14)
R14_OI_CH4 "2k" 6-0805_M 4861.54,2575 r90 top value=1.91k (schematic designator R14)
R15_IO_CH1 "0" 6-0805_M 6340,4690 r180 top (schematic designator R15)
R15_IO_CH2 "0" 6-0805_M 6340,2020 r180 top (schematic designator R15)
R15_OI_CH1 "0" 6-0805_M 6340,6110 r180 top (schematic designator R15)
R15_OI_CH2 "0" 6-0805_M 6340,5405 r180 top (schematic designator R15)
R15_OI_CH3 "0" 6-0805_M 6340.63,3450 r180 top (schematic designator R15)
R15_OI_CH4 "0" 6-0805_M 6340,2735 r180 top (schematic designator R15)
R16_IO_CH1 "RPot8" "POT SMD" 5161.54,4525 r180 top value=200 (schematic designator R16)
R16_IO_CH2 "RPot8" "POT SMD" 5161.54,1855 r180 top value=200 (schematic designator R16)
R16_OI_CH1 "RPot8" "POT SMD" 5160,5960 r180 top value=200 (schematic designator R16)
R16_OI_CH2 "RPot8" "POT SMD" 5161.54,5240 r180 top value=200 (schematic designator R16)
R16_OI_CH3 "RPot8" "POT SMD" 5162.17,3285 r180 top value=200 (schematic designator R16)
R16_OI_CH4 "RPot8" "POT SMD" 5161.54,2570 r180 top value=200 (schematic designator R16)
R17_IO_CH1 "9.09k" 6-0805_M 4861.54,4860 r270 top value=9.53k (schematic designator R17)
R17_IO_CH2 "9.09k" 6-0805_M 4861.54,2190 r270 top value=9.53k (schematic designator R17)
R17_OI_CH1 "9.09k" 6-0805_M 4861.54,6290 r270 top value=9.53k (schematic designator R17)
R17_OI_CH2 "9.09k" 6-0805_M 4861.54,5575 r270 top value=9.53k (schematic designator R17)
R17_OI_CH3 "9.09k" 6-0805_M 4862.17,3620 r270 top value=9.53k (schematic designator R17)
R17_OI_CH4 "9.09k" 6-0805_M 4861.54,2905 r270 top value=9.53k (schematic designator R17)
R18_IO_CH1 "RPot8" "POT SMD" 5161.54,4875 r180 top value=1k (schematic designator R18)
R18_IO_CH2 "RPot8" "POT SMD" 5161.54,2205 r180 top value=1k (schematic designator R18)
R18_OI_CH1 "RPot8" "POT SMD" 5160,6305 r180 top value=1k (schematic designator R18)
R18_OI_CH2 "RPot8" "POT SMD" 5161.54,5590 r180 top value=1k (schematic designator R18)
R18_OI_CH3 "RPot8" "POT SMD" 5162.17,3635 r180 top value=1k (schematic designator R18)
R18_OI_CH4 "RPot8" "POT SMD" 5161.54,2920 r180 top value=1k (schematic designator R18)
R19_IO_CH1 "0" 6-0805_M 1725,4680 r180 top (schematic designator R19)
R19_IO_CH2 "0" 6-0805_M 1725,2010 r180 top (schematic designator R19)
R19_OI_CH1 "0" 6-0805_M 1725,6110 r180 top (schematic designator R19)
R19_OI_CH2 "0" 6-0805_M 1725,5395 r180 top (schematic designator R19)
R19_OI_CH3 "0" 6-0805_M 1725.63,3440 r180 top (schematic designator R19)
R19_OI_CH4 "0" 6-0805_M 1725,2725 r180 top (schematic designator R19)
R20_IO_CH1 "0" 6-0805_M 1730,4805 r180 top (schematic designator R20)
R20_IO_CH2 "0" 6-0805_M 1730,2135 r180 top (schematic designator R20)
R20_OI_CH1 "0" 6-0805_M 1730,6235 r180 top (schematic designator R20)
R20_OI_CH2 "0" 6-0805_M 1730,5520 r180 top (schematic designator R20)
R20_OI_CH3 "0" 6-0805_M 1730.63,3565 r180 top (schematic designator R20)
R20_OI_CH4 "0" 6-0805_M 1730,2850 r180 top (schematic designator R20)
R21_IO_CH1 "0" 6-0805_M 6335,4590 r180 top (schematic designator R21)
R21_IO_CH2 "0" 6-0805_M 6335,1920 r180 top (schematic designator R21)
R21_OI_CH1 "0" 6-0805_M 6340,6025 r180 top (schematic designator R21)
R21_OI_CH2 "0" 6-0805_M 6335,5305 r180 top (schematic designator R21)
R21_OI_CH3 "0" 6-0805_M 6335.63,3350 r180 top (schematic designator R21)
R21_OI_CH4 "0" 6-0805_M 6335,2635 r180 top (schematic designator R21)
"R27_Side A power supply and references" "1.5R" R1206 2610,3885 r0 top (schematic designator R27)
"R27_Side B power supply and references" "1.5R" R1206 5135,4070 r180 top (schematic designator R27)
"R28_Side A power supply and references" "1.5R" R1206 2610,4055 r0 top (schematic designator R28)
"R28_Side B power supply and references" "1.5R" R1206 5135,3900 r180 top (schematic designator R28)
TP1_IO_CH1 "Vero Eyelet Test Point" "TEST PT SMD" 1911.54,4710 r90 top (schematic designator TP1)
TP1_IO_CH2 "Vero Eyelet Test Point" "TEST PT SMD" 1911.54,2040 r90 top (schematic designator TP1)
TP1_OI_CH1 "Vero Eyelet Test Point" "TEST PT SMD" 1911.54,6140 r90 top (schematic designator TP1)
TP1_OI_CH2 "Vero Eyelet Test Point" "TEST PT SMD" 1911.54,5425 r90 top (schematic designator TP1)
TP1_OI_CH3 "Vero Eyelet Test Point" "TEST PT SMD" 1912.17,3470 r90 top (schematic designator TP1)
TP1_OI_CH4 "Vero Eyelet Test Point" "TEST PT SMD" 1911.54,2755 r90 top (schematic designator TP1)
TP2_IO_CH1 "Vero Eyelet Test Point" "TEST PT SMD" 2086.54,4355 r90 top (schematic designator TP2)
TP2_IO_CH2 "Vero Eyelet Test Point" "TEST PT SMD" 2086.54,1685 r90 top (schematic designator TP2)
TP2_OI_CH1 "Vero Eyelet Test Point" "TEST PT SMD" 2086.54,5785 r90 top (schematic designator TP2)
TP2_OI_CH2 "Vero Eyelet Test Point" "TEST PT SMD" 2086.54,5070 r90 top (schematic designator TP2)
TP2_OI_CH3 "Vero Eyelet Test Point" "TEST PT SMD" 2087.17,3115 r90 top (schematic designator TP2)
TP2_OI_CH4 "Vero Eyelet Test Point" "TEST PT SMD" 2086.54,2400 r90 top (schematic designator TP2)
TP3_IO_CH1 "Vero Eyelet Test Point" "TEST PT SMD" 2621.54,4840 r0 top (schematic designator TP3)
TP3_IO_CH2 "Vero Eyelet Test Point" "TEST PT SMD" 2621.54,2170 r0 top (schematic designator TP3)
TP3_OI_CH1 "Vero Eyelet Test Point" "TEST PT SMD" 2621.54,6270 r0 top (schematic designator TP3)
TP3_OI_CH2 "Vero Eyelet Test Point" "TEST PT SMD" 2621.54,5555 r0 top (schematic designator TP3)
TP3_OI_CH3 "Vero Eyelet Test Point" "TEST PT SMD" 2622.17,3600 r0 top (schematic designator TP3)
TP3_OI_CH4 "Vero Eyelet Test Point" "TEST PT SMD" 2621.54,2885 r0 top (schematic designator TP3)
TP4_IO_CH1 "Vero Eyelet Test Point" "TEST PT SMD" 4851.54,4695 r270 top (schematic designator TP4)
TP4_IO_CH2 "Vero Eyelet Test Point" "TEST PT SMD" 4851.54,2025 r270 top (schematic designator TP4)
TP4_OI_CH1 "Vero Eyelet Test Point" "TEST PT SMD" 4851.54,6125 r270 top (schematic designator TP4)
TP4_OI_CH2 "Vero Eyelet Test Point" "TEST PT SMD" 4851.54,5410 r270 top (schematic designator TP4)
TP4_OI_CH3 "Vero Eyelet Test Point" "TEST PT SMD" 4852.17,3455 r270 top (schematic designator TP4)
TP4_OI_CH4 "Vero Eyelet Test Point" "TEST PT SMD" 4851.54,2740 r270 top (schematic designator TP4)
TP5_IO_CH1 "Vero Eyelet Test Point" "TEST PT SMD" 6345,4785 r180 top (schematic designator TP5)
TP5_IO_CH2 "Vero Eyelet Test Point" "TEST PT SMD" 6345,2115 r180 top (schematic designator TP5)
TP5_OI_CH1 "Vero Eyelet Test Point" "TEST PT SMD" 6410,6235 r270 top (schematic designator TP5)
TP5_OI_CH2 "Vero Eyelet Test Point" "TEST PT SMD" 6345,5500 r180 top (schematic designator TP5)
TP5_OI_CH3 "Vero Eyelet Test Point" "TEST PT SMD" 6345.63,3545 r180 top (schematic designator TP5)
TP5_OI_CH4 "Vero Eyelet Test Point" "TEST PT SMD" 6345,2830 r180 top (schematic designator TP5)
"TP+_Side A power supply and references" "Vero Eyelet Test Point" "TEST PT SMD" 1990,3815 r180 top (schematic designator TP+)
"TP+_Side B power supply and references" "Vero Eyelet Test Point" "TEST PT SMD" 5755,4140 r0 top (schematic designator TP+)
"TP-_Side A power supply and references" "Vero Eyelet Test Point" "TEST PT SMD" 1990,4135 r180 top (schematic designator TP-)
"TP-_Side B power supply and references" "Vero Eyelet Test Point" "TEST PT SMD" 5755,3820 r0 top (schematic designator TP-)
"TPCOM_Side A power supply and references" "Vero Eyelet Test Point" PAD-110-52 1990,3975 r270 top (schematic designator TPCOM)
"TPCOM_Side B power supply and references" "Vero Eyelet Test Point" PAD-110-52 5755,3980 r90 top (schematic designator TPCOM)
U1_IO_CH1 "ADA4177-2" SO-G8 2126.54,4720 r0 top (schematic designator U1)
U1_IO_CH2 "ADA4177-2" SO-G8 2126.54,2050 r0 top (schematic designator U1)
U1_OI_CH1 "ADA4177-2" SO-G8 2126.54,6150 r0 top (schematic designator U1)
U1_OI_CH2 "ADA4177-2" SO-G8 2126.54,5435 r0 top (schematic designator U1)
U1_OI_CH3 "ADA4177-2" SO-G8 2127.17,3480 r0 top (schematic designator U1)
U1_OI_CH4 "ADA4177-2" SO-G8 2126.54,2765 r0 top (schematic designator U1)
U2_IO_CH1 "ADA4625" SO-G8 3016.54,4715 r0 top (schematic designator U2)
U2_IO_CH2 "ADA4625" SO-G8 3016.54,2045 r0 top (schematic designator U2)
U2_OI_CH1 "ADA4625" SO-G8 3016.54,6145 r0 top (schematic designator U2)
U2_OI_CH2 "ADA4625" SO-G8 3016.54,5430 r0 top (schematic designator U2)
U2_OI_CH3 "ADA4625" SO-G8 3017.17,3475 r0 top (schematic designator U2)
U2_OI_CH4 "ADA4625" SO-G8 3016.54,2760 r0 top (schematic designator U2)
U3_IO_CH1 "HCNR201" DIP-8GW 3871.54,4675 r0 top (schematic designator U3)
U3_IO_CH2 "HCNR201" DIP-8GW 3871.54,2005 r0 top (schematic designator U3)
U3_OI_CH1 "HCNR201" DIP-8GW 3871.54,6105 r0 top (schematic designator U3)
U3_OI_CH2 "HCNR201" DIP-8GW 3871.54,5390 r0 top (schematic designator U3)
U3_OI_CH3 "HCNR201" DIP-8GW 3872.17,3435 r0 top (schematic designator U3)
U3_OI_CH4 "HCNR201" DIP-8GW 3871.54,2720 r0 top (schematic designator U3)
U4_IO_CH1 "ADA4625" SO-G8 4586.54,4600 r0 top (schematic designator U4)
U4_IO_CH2 "ADA4625" SO-G8 4586.54,1930 r0 top (schematic designator U4)
U4_OI_CH1 "ADA4625" SO-G8 4586.54,6030 r0 top (schematic designator U4)
U4_OI_CH2 "ADA4625" SO-G8 4586.54,5315 r0 top (schematic designator U4)
U4_OI_CH3 "ADA4625" SO-G8 4587.17,3360 r0 top (schematic designator U4)
U4_OI_CH4 "ADA4625" SO-G8 4586.54,2645 r0 top (schematic designator U4)
U5_IO_CH1 "ADA4177-1" SO-G8 6100,4655 r0 top (schematic designator U5)
U5_IO_CH2 "ADA4177-1" SO-G8 6100,1985 r0 top (schematic designator U5)
U5_OI_CH1 "ADA4177-1" SO-G8 6100,6085 r0 top (schematic designator U5)
U5_OI_CH2 "ADA4177-1" SO-G8 6100,5370 r0 top (schematic designator U5)
U5_OI_CH3 "ADA4177-1" SO-G8 6100.63,3415 r0 top (schematic designator U5)
U5_OI_CH4 "ADA4177-1" SO-G8 6100,2700 r0 top (schematic designator U5)
"U6_Side A power supply and references" "LT1021B-10" SO-G8 1785,3895 r90 top (schematic designator U6)
"U6_Side B power supply and references" "LT1021B-10" SO-G8 6005,4070 r180 top (schematic designator U6)

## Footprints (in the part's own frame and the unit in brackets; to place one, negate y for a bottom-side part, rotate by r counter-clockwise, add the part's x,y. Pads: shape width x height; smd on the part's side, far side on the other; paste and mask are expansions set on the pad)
6-0805_M [mm] "Chip Resistor, Body 2.0x1.2mm, IPC Low Density"
  rect 1.4x1.5 smd: 1(-1,0) 2(1,0)
  silkscreen extent 0,-0.65 0,0.65, body extent -1.07,-0.7 1.07,0.7, height 0.7
CC3216 [mm]
  rect 1.2x1.8 smd: 1(-1.3,0) 2(1.3,0)
  silkscreen extent -2.17,-1.5 2.17,1.5
CC7343 [mm]
  rect 2x3 smd: 1(0,0) 2(6,0)
  silkscreen extent -2.1,-2.2 7.3,2.2
DIP-8GW [mil] "DIP-8 Gull Wing"
  rect 100x60 smd: 1(-222,150) 2(-222,50) 3(-222,-50) 4(-222,-150) 5(222,-150) 6(222,-50) 7(222,50) 8(222,150)
  silkscreen extent -223,-230 222,230
"HDR1X3 SMD" [mil] "3 pos header surface mount"
  rect 50x116 smd: 1(0,0) 2(100,-140) 3(200,0)
  silkscreen extent -50,-215 250,75
"HDR1X6 SMD" [mil] "6 pos header surface mount"
  rect 50x116 smd: 1(0,0) 2(100,-140) 3(200,0) 4(300,-140) 5(400,0) 6(500,-140)
  silkscreen extent -50,-215 550,75
PAD-110-52 [mil] "Pad 100mil Diameter 52mil Hole"
  round 110 hole 52: 1(0,0)
  silkscreen extent -66,-66 66,66
"POT SMD" [mm] "Potentiometer Surface Mount"
  rect 1x3 smd: 1(0,0) 2(2.54,4.5) 3(5.08,0)
  silkscreen extent -1.27,-1.91 6.35,6.4
R1206 [mm]
  rect 1.6x1.8 smd: 1(-1.4,0) 2(1.4,0)
  silkscreen extent -2.5,-1.2 2.5,1.2, body extent -1.6,-0.8 1.6,0.8, height 1
SMAJ [mil] "DO-214AC Diode package"
  rect 70x58 smd: 1(-80,0) 2(80,0)
  silkscreen extent -80,-70 110,70
SMB_Male_Vertical [mil] "Vertical Male SMB Connector"
  round 64.97 / inner round 60 / far side round 64.97 hole 43.31: 1(0,0)
  round 82.68 / inner round 60 / far side round 82.68 hole 55.12: 2(-100,-100) 2(-100,100) 2(100,-100) 2(100,100)
  silkscreen extent -135,-135 135,135
SO-G8 [mm] "SOIC, 8-Leads, Body 5.0x4.0mm (max), Pitch 1.27mm, IPC Medium Density"
  rect 2.2x0.6 smd: 1(-2.4,1.905) 2(-2.4,0.635) 3(-2.4,-0.635) 4(-2.4,-1.905) 5(2.4,-1.905) 6(2.4,-0.635) 7(2.4,0.635) 8(2.4,1.905)
  silkscreen extent -2.52,-2.5 0.9,2.88, body extent -3.01,-2.5 3.01,2.5, height 1.75
SOD-123 [mm]
  rect 0.7x1.2 smd: 1(-1.85,0) 2(1.85,0)
  silkscreen extent -2.5,-1.2 2.5,1.2, body extent -1.93,-0.81 1.93,0.89, height 1.44
"TEST PT SMD" [mm] "Test Point SMD Keystone 5015"
  rect 3.53x1.88 smd: 1(0,0)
